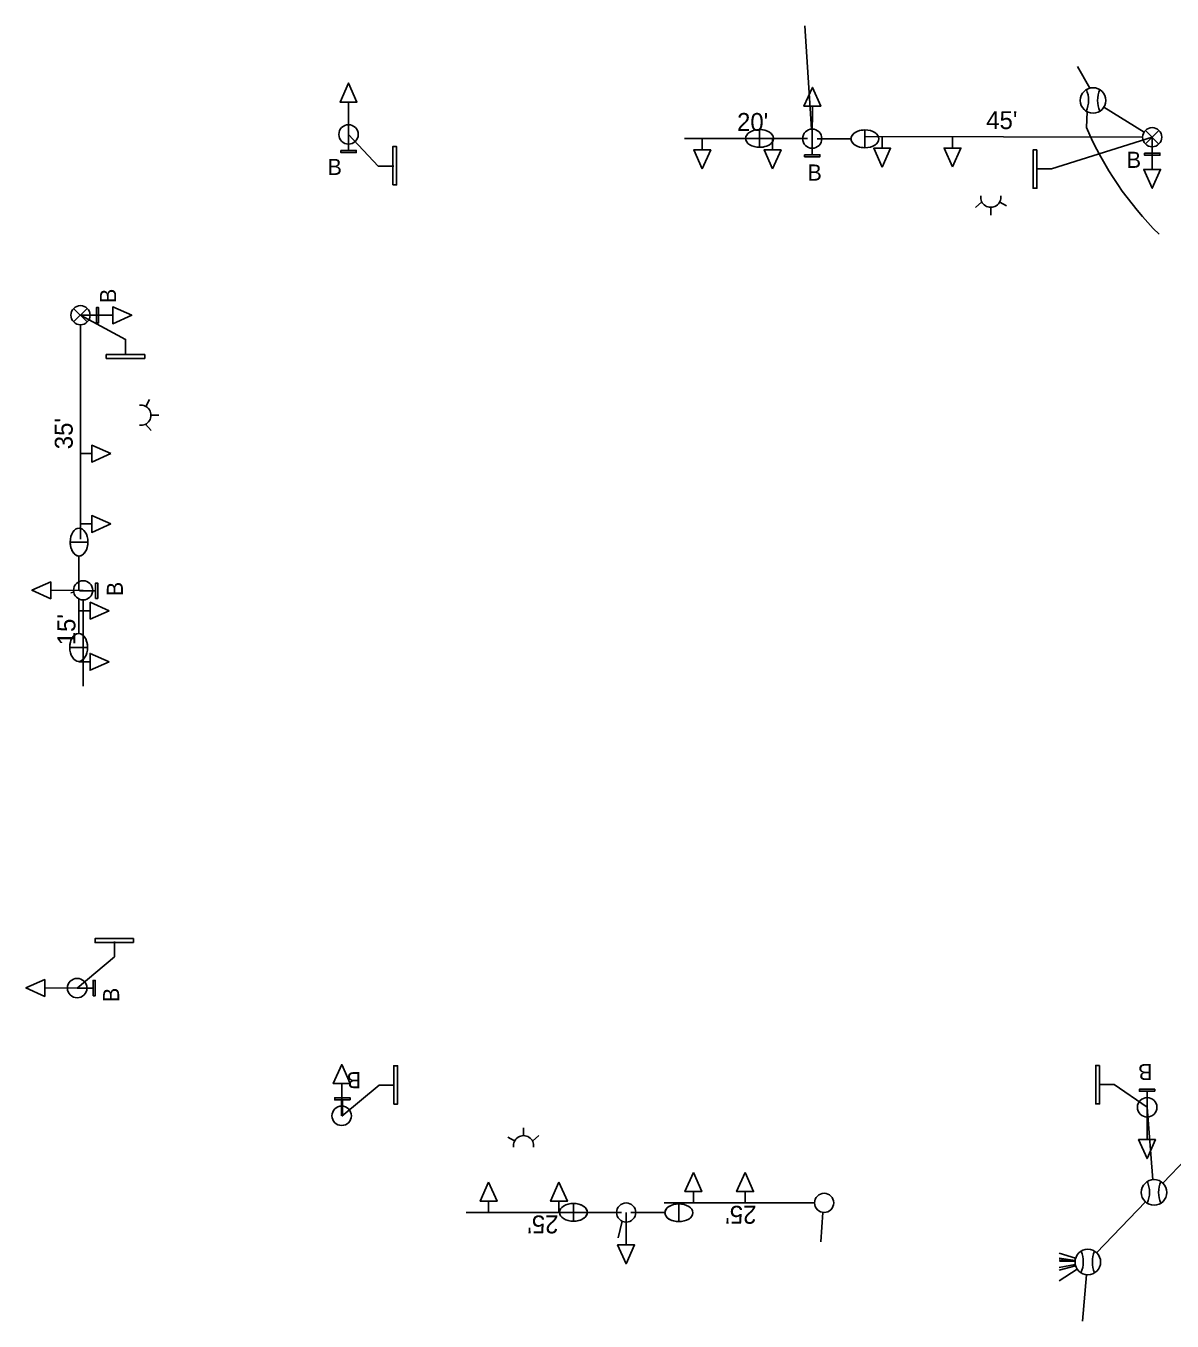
# Model space of a CAD drawing. Extents: x 596176 to 605330, y 332416 to 402398.
# Drawn here: x 601986.2 to 602165.4, y 366038.8 to 366241.3 of the extents above; entities that cross this region are included whole.
import ezdxf

# ---------------------------------------------------------------- set-up
doc = ezdxf.new("R2010")
doc.units = 0
for name, color, linetype in [('P_LTG', 7, 'Continuous'), ('P_SIG', 7, 'Continuous'), ('P_SIG_Bold', 7, 'Continuous'), ('P_SIG_Conduit', 7, 'Continuous'), ('P_SIG_Loops', 7, 'Continuous')]:
    doc.layers.add(name, color=color, linetype=linetype)

msp = doc.modelspace()

# ---------------------------------------------------------------- linework, layer by layer
at = {"layer": 'P_LTG'}
for p, q in [((602100.92, 366225.11), (602100.92, 366222.33)), ((602117.4, 366222.27), (602117.4, 366225.05)), ((602108.41, 366223.71), (602103.11, 366223.71)), ((602109.92, 366223.67), (602115.21, 366223.67)), ((601995.88, 366160.6), (601993.1, 366160.6)), ((601994.48, 366153.12), (601994.48, 366158.41)), ((601994.45, 366151.61), (601994.45, 366146.32)), ((601993.04, 366144.12), (601995.82, 366144.12)), ((602071.82, 366057.17), (602071.82, 366054.39)), ((602088.3, 366054.33), (602088.3, 366057.11)), ((602079.31, 366055.77), (602074.01, 366055.77)), ((602080.81, 366055.74), (602086.11, 366055.74))]:
    msp.add_line(p, q, dxfattribs=at)
for centre, major_axis in [((602100.92, 366223.72), (-2.18, 0)), ((602117.4, 366223.66), (2.18, 0)), ((601994.49, 366160.6), (0, 2.18)), ((601994.43, 366144.12), (0, -2.18)), ((602071.82, 366055.78), (-2.18, 0)), ((602088.3, 366055.72), (2.18, 0))]:
    msp.add_ellipse(centre, major_axis=major_axis, ratio=0.636439, dxfattribs=at)
for centre, major_axis in [((602100.92, 366223.72), (-2.18, 0)), ((602117.4, 366223.66), (2.18, 0)), ((601994.49, 366160.6), (0, 2.18)), ((601994.43, 366144.12), (0, -2.18)), ((602071.82, 366055.78), (-2.18, 0)), ((602088.3, 366055.72), (2.18, 0))]:
    msp.add_ellipse(centre, major_axis=major_axis, ratio=0.636439, start_param=1.570796, end_param=4.712389, dxfattribs=at)
at = {"layer": 'P_SIG'}
for p, q in [((602036.65, 366229.41), (602036.64, 366224.35)), ((602109.18, 366228.75), (602109.16, 366223.69)), ((602041.3, 366219.41), (602036.64, 366224.36)), ((602036.64, 366224.35), (602036.64, 366221.85)), ((602091.96, 366221.92), (602091.96, 366223.69)), ((602102.96, 366221.92), (602102.96, 366223.69)), ((602109.16, 366223.68), (602109.16, 366221.18)), ((602120.1, 366222.18), (602120.1, 366223.95)), ((602131.1, 366222.22), (602131.1, 366223.99)), ((602146.58, 366218.96), (602162.33, 366223.92)), ((602162.32, 366218.89), (602162.33, 366223.95)), ((602162.33, 366223.92), (602162.33, 366221.42)), ((602041.3, 366219.41), (602043.7, 366219.41)), ((602146.58, 366218.96), (602144.18, 366218.96)), ((602135.69, 366213.8), (602134.7, 366212.92)), ((602137.1, 366212.95), (602137.1, 366211.72)), ((602138.48, 366213.77), (602139.55, 366213.18)), ((601994.72, 366196.08), (601997.22, 366196.08)), ((602001.76, 366192.27), (601994.72, 366196.08)), ((601999.77, 366196.06), (601994.72, 366196.08)), ((602001.76, 366192.33), (602001.76, 366189.93)), ((602004.92, 366181.82), (602005.52, 366182.9)), ((602005.74, 366180.45), (602006.97, 366180.45)), ((602004.89, 366179.03), (602005.77, 366178.04)), ((601996.49, 366174.44), (601994.72, 366174.44)), ((601996.49, 366163.44), (601994.72, 366163.44)), ((601990.07, 366153.06), (601995.13, 366153.04)), ((601994.58, 366152.99), (601997.08, 366152.99)), ((601996.24, 366149.86), (601994.47, 366149.86)), ((601996.23, 366141.86), (601994.46, 366141.86)), ((602000.04, 366095.72), (602000.04, 366098.12)), ((602000.04, 366095.72), (601994.2, 366090.85)), ((601989.14, 366090.87), (601994.2, 366090.85)), ((601994.2, 366090.85), (601996.7, 366090.85)), ((602035.57, 366075.93), (602035.56, 366070.88)), ((602041.44, 366075.66), (602035.6, 366070.8)), ((602041.44, 366075.66), (602043.84, 366075.66)), ((602156.37, 366075.8), (602153.97, 366075.8)), ((602156.37, 366075.8), (602161.54, 366072.21)), ((602035.68, 366070.86), (602035.68, 366073.36)), ((602161.53, 366072.21), (602161.53, 366074.71)), ((602161.52, 366067.16), (602161.54, 366072.21)), ((602064, 366067.78), (602064, 366069.01)), ((602062.62, 366066.96), (602061.55, 366067.55)), ((602065.41, 366066.93), (602066.4, 366067.81)), ((602090.57, 366059.03), (602090.57, 366057.26)), ((602098.66, 366059.03), (602098.66, 366057.26)), ((602058.55, 366057.52), (602058.55, 366055.75)), ((602069.55, 366057.52), (602069.55, 366055.75)), ((602080.05, 366050.69), (602080.06, 366055.75))]:
    msp.add_line(p, q, dxfattribs=at)
for points in [[(602036.65, 366232.37), (602037.96, 366229.41), (602035.33, 366229.41), (602036.65, 366232.37)], [(602037.96, 366229.41), (602036.65, 366232.37), (602035.33, 366229.41), (602037.96, 366229.41)], [(602109.18, 366231.71), (602110.49, 366228.75), (602107.86, 366228.75), (602109.18, 366231.71)], [(602109.18, 366231.71), (602110.49, 366228.75), (602107.86, 366228.75), (602109.18, 366231.71)], [(602110.49, 366228.75), (602109.18, 366231.71), (602107.86, 366228.75), (602110.49, 366228.75)], [(602162.33, 366215.93), (602161.01, 366218.89), (602163.64, 366218.89), (602162.33, 366215.93)], [(602162.33, 366215.93), (602161.01, 366218.89), (602163.64, 366218.89), (602162.33, 366215.93)], [(602161.01, 366218.89), (602162.33, 366215.93), (602163.64, 366218.89), (602161.01, 366218.89)], [(602002.73, 366196.06), (601999.77, 366194.75), (601999.77, 366197.38), (602002.73, 366196.06)], [(602002.73, 366196.06), (601999.77, 366194.75), (601999.77, 366197.38), (602002.73, 366196.06)], [(601999.77, 366194.75), (602002.73, 366196.06), (601999.77, 366197.38), (601999.77, 366194.75)], [(601987.11, 366153.06), (601990.07, 366154.37), (601990.07, 366151.74), (601987.11, 366153.06)], [(601987.11, 366153.06), (601990.07, 366154.37), (601990.07, 366151.74), (601987.11, 366153.06)], [(601990.07, 366154.37), (601987.11, 366153.06), (601990.07, 366151.74), (601990.07, 366154.37)], [(601986.18, 366090.87), (601989.14, 366092.18), (601989.14, 366089.55), (601986.18, 366090.87)], [(601989.14, 366092.18), (601986.18, 366090.87), (601989.14, 366089.55), (601989.14, 366092.18)], [(602035.57, 366078.89), (602036.89, 366075.93), (602034.25, 366075.93), (602035.57, 366078.89)], [(602036.89, 366075.93), (602035.57, 366078.89), (602034.25, 366075.93), (602036.89, 366075.93)], [(602161.52, 366064.2), (602160.21, 366067.16), (602162.84, 366067.16), (602161.52, 366064.2)], [(602160.21, 366067.16), (602161.52, 366064.2), (602162.84, 366067.16), (602160.21, 366067.16)], [(602080.05, 366047.73), (602078.73, 366050.69), (602081.37, 366050.69), (602080.05, 366047.73)], [(602080.05, 366047.73), (602078.73, 366050.69), (602081.37, 366050.69), (602080.05, 366047.73)], [(602078.73, 366050.69), (602080.05, 366047.73), (602081.37, 366050.69), (602078.73, 366050.69)]]:
    msp.add_lwpolyline(points, dxfattribs=at)
for points in [[(602035.44, 366221.85), (602037.84, 366221.85), (602037.84, 366221.52), (602035.44, 366221.52)], [(602043.56, 366216.45), (602043.56, 366222.45), (602044.16, 366222.45), (602044.16, 366216.45)], [(602091.96, 366218.96), (602090.64, 366221.92), (602093.28, 366221.92)], [(602102.96, 366218.96), (602101.64, 366221.92), (602104.28, 366221.92)], [(602107.96, 366221.18), (602110.36, 366221.18), (602110.36, 366220.86), (602107.96, 366220.86)], [(602120.1, 366219.22), (602118.79, 366222.18), (602121.42, 366222.18)], [(602131.1, 366219.26), (602129.78, 366222.22), (602132.42, 366222.22)], [(602144.31, 366221.92), (602144.31, 366215.92), (602143.71, 366215.92), (602143.71, 366221.92)], [(602161.13, 366221.42), (602163.53, 366221.42), (602163.53, 366221.09), (602161.13, 366221.09)], [(601997.21, 366194.88), (601997.21, 366197.28), (601997.54, 366197.28), (601997.54, 366194.88)], [(601998.76, 366189.93), (602004.76, 366189.93), (602004.76, 366189.33), (601998.76, 366189.33)], [(601999.44, 366174.44), (601996.49, 366173.12), (601996.49, 366175.75)], [(601999.44, 366163.44), (601996.49, 366162.12), (601996.49, 366164.75)], [(601997.08, 366151.79), (601997.08, 366154.19), (601997.41, 366154.19), (601997.41, 366151.79)], [(601999.2, 366149.86), (601996.24, 366148.55), (601996.24, 366151.18)], [(601999.19, 366141.86), (601996.23, 366140.55), (601996.23, 366143.18)], [(602003, 366097.98), (601997, 366097.98), (601997, 366098.58), (602003, 366098.58)], [(601996.7, 366089.65), (601996.7, 366092.05), (601997.02, 366092.05), (601997.02, 366089.65)], [(602043.71, 366072.71), (602043.71, 366078.71), (602044.31, 366078.71), (602044.31, 366072.7)], [(602154.1, 366078.75), (602154.1, 366072.75), (602153.5, 366072.75), (602153.5, 366078.75)], [(602162.73, 366074.71), (602160.33, 366074.71), (602160.33, 366075.04), (602162.73, 366075.04)], [(602036.88, 366073.36), (602034.48, 366073.36), (602034.48, 366073.69), (602036.88, 366073.69)], [(602090.57, 366061.99), (602091.88, 366059.03), (602089.25, 366059.03)], [(602098.66, 366061.99), (602099.98, 366059.03), (602097.34, 366059.03)], [(602058.55, 366060.48), (602059.87, 366057.52), (602057.23, 366057.52)], [(602069.55, 366060.48), (602070.87, 366057.52), (602068.24, 366057.52)]]:
    msp.add_lwpolyline(points, close=True, dxfattribs=at)
for centre, radius in [((602153.08, 366229.66), 2), ((602036.64, 366224.35), 1.52), ((602036.64, 366224.35), 1.52), ((602036.64, 366224.35), 1.52), ((601994.2, 366090.85), 1.52), ((601994.2, 366090.85), 1.52), ((601994.2, 366090.85), 1.52), ((602161.54, 366072.21), 1.52), ((602161.54, 366072.21), 1.52), ((602161.54, 366072.21), 1.52), ((602035.56, 366070.88), 1.52), ((602035.56, 366070.88), 1.52), ((602035.56, 366070.88), 1.52), ((602162.62, 366058.9), 2), ((602152.26, 366048.01), 2)]:
    msp.add_circle(centre, radius, dxfattribs=at)
for centre, radius, start, end in [((602148.01, 366229.69), 4.36, 336.6741, 22.5272), ((602158.15, 366229.7), 4.36, 157.5751, 203.4282), ((602036.64, 366224.35), 1.52, 90, 270), ((602036.64, 366224.35), 1.52, 270, 90), ((602137.09, 366214.53), 1.58, 172.2462, 7.7538), ((602004.16, 366180.44), 1.58, 262.2462, 97.7538), ((601994.2, 366090.85), 1.52, 0, 180), ((601994.2, 366090.85), 1.52, 180, 0), ((602161.54, 366072.21), 1.52, 90, 270), ((602161.54, 366072.21), 1.52, 270, 90), ((602035.56, 366070.88), 1.52, 90, 270), ((602035.56, 366070.88), 1.52, 270, 90), ((602064.01, 366066.2), 1.58, 352.2462, 187.7538), ((602157.55, 366058.94), 4.36, 336.6741, 22.5272), ((602167.69, 366058.94), 4.36, 157.5751, 203.4282), ((602147.19, 366048.04), 4.36, 336.6741, 22.5272), ((602157.33, 366048.05), 4.36, 157.5751, 203.4282)]:
    msp.add_arc(centre, radius, start, end, dxfattribs=at)
at = {"layer": 'P_SIG_Bold'}
for p, q in [((602163.39, 366224.97), (602161.26, 366222.86)), ((602161.27, 366224.98), (602163.39, 366222.85)), ((602089.16, 366223.69), (602107.66, 366223.69)), ((602117.33, 366224.03), (602160.83, 366223.92)), ((601993.65, 366195.02), (601995.78, 366197.14)), ((601993.65, 366197.14), (601995.78, 366195.02)), ((601994.72, 366161.08), (601994.72, 366194.58)), ((601995.13, 366138.05), (601995.13, 366151.55)), ((602086.02, 366057.26), (602109.52, 366057.26)), ((602055.06, 366055.75), (602078.56, 366055.75))]:
    msp.add_line(p, q, dxfattribs=at)
for centre in [(602109.16, 366223.69), (602162.33, 366223.92), (601994.72, 366196.08), (601995.13, 366153.05), (602111.02, 366057.26), (602080.06, 366055.75)]:
    msp.add_circle(centre, 1.5, dxfattribs=at)
at = {"layer": 'P_SIG_Conduit'}
for p, q in [((602109.06, 366225.19), (602108.01, 366241.32)), ((602150.67, 366234.99), (602152.56, 366231.59)), ((602161.05, 366224.71), (602154.78, 366228.6)), ((601993.66, 366152.76), (601993.21, 366152.68)), ((602161.54, 366072.21), (602162.45, 366060.89)), ((602164.01, 366060.34), (602167.68, 366064.2)), ((602153.64, 366049.46), (602161.26, 366057.44)), ((602110.5, 366051.19), (602110.84, 366055.77)), ((602078.81, 366051.8), (602079.45, 366054.38)), ((602147.83, 366048.16), (602150.26, 366048.07)), ((602151.43, 366038.77), (602152.06, 366046.02))]:
    msp.add_line(p, q, dxfattribs=at)
msp.add_lwpolyline([(602152.18, 366227.87), (602152.05, 366225.41)], dxfattribs=at)
msp.add_arc((602201.45, 366246.82), 53.84, 203.4321, 225.0233, dxfattribs=at)
at = {"layer": 'P_SIG_Loops'}
for p, q in [((602147.76, 366048.59), (602150.27, 366048.25)), ((602147.77, 366049.4), (602150.35, 366048.59)), ((602147.76, 366048.38), (602150.27, 366048.16)), ((602147.76, 366047.17), (602150.3, 366047.63)), ((602147.76, 366046.72), (602150.34, 366047.44)), ((602147.76, 366045.05), (602150.59, 366046.91))]:
    msp.add_line(p, q, dxfattribs=at)

# ---------------------------------------------------------------- texts
at = {"layer": 'P_SIG'}
for rotation, p in [(360, (602158.34, 366219.12)), (360, (602033.35, 366218.01)), (0.0006, (602108.41, 366217.13)), (90, (602000.29, 366197.98)), (90, (602001.35, 366152.14)), (90.0008, (602000.77, 366088.66)), (180, (602162.38, 366078.98)), (180.0008, (602038.62, 366077.71))]:
    msp.add_text('B', height=2.52, rotation=rotation, dxfattribs=at).set_placement(p)
at = {"layer": 'P_SIG_Bold'}
msp.add_text("20'", height=2.8, dxfattribs=at).set_placement((602097.4, 366224.9))
for s, rotation, p in [("45'", 359.8588, (602136.37, 366225.19)), ("35'", 90, (601993.5, 366175.12)), ("15'", 90, (601993.92, 366144.46)), ("25'", 180, (602100.43, 366056.8)), ("25'", 180, (602069.47, 366055.29))]:
    msp.add_text(s, height=2.8, rotation=rotation, dxfattribs=at).set_placement(p)

doc.saveas('drawing.dxf')
